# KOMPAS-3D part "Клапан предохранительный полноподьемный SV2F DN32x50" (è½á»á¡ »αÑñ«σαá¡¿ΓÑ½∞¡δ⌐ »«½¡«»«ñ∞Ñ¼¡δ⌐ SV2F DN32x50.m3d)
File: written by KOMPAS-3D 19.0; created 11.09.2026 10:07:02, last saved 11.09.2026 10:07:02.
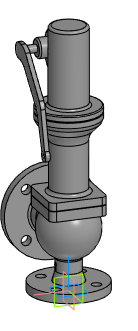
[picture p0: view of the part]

Document properties: Автор: elist; Организация: HP; Полное имя файла: Z:\3.Личные\sachek\Dendor\_3D для проектировщиков\5.9 SV2F. Клапан предохранительный полноподьемный\SV2F_STP\Клапан предохранительный полноподьемный SV2F DN32x50.m3d

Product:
- Part/product: Клапан предохранительный полноподьемный SV2F DN32x50

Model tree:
1. Операция без истории:1  (labels: Клапан предохранительный полноподьемный SV2F DN32x50)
